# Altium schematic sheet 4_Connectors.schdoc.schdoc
size 309 x 223 mm; Symbol: Artery_A4; Device: Artery_A4; @Page Count: 4; @Create Date: 2024-01-02; @Page Name: Connectors; @Project Name: AT-START-L021; @Update Date: 2024-02-21; @Schematic Name: AT-START-L021_V1.0; @Page No: 4; Company: Artery Technology; Drawed: SD; Version: 1.0; Page Size: A4
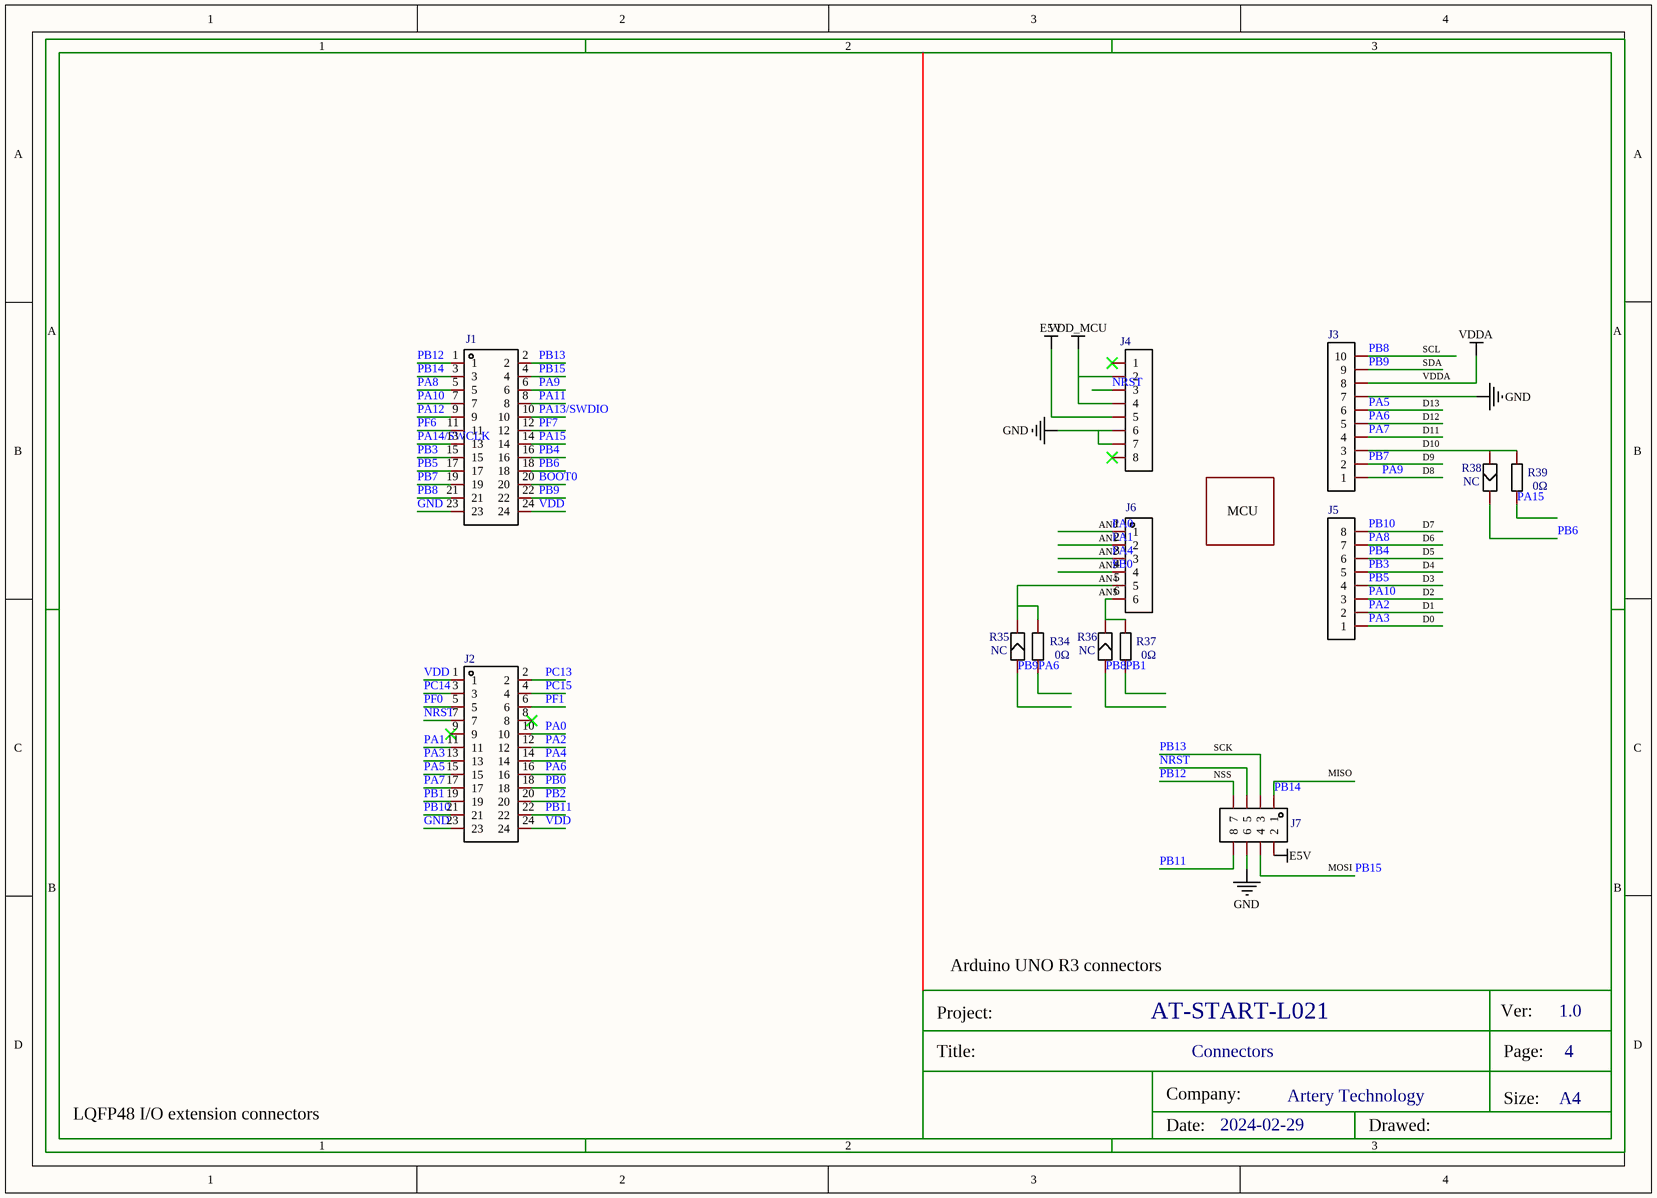
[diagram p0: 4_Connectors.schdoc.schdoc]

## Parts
J1  PZ254V-12-24P  [HDR-TH_24P-P2.54-V-M-R2-C12-S2.54]  (value not drawn)
J2  PZ254V-12-24P  [HDR-TH_24P-P2.54-V-M-R2-C12-S2.54]  (value not drawn)
J3  2.54-1*10P母  [AT-START-Connector 1x10]  (value not drawn)
J4  2.54-1*8P母环保  [AT-START-Connector 1x8]  (value not drawn)
J5  2.54-1*8P母环保  [AT-START-Connector 1x8]  (value not drawn)
J6  2.54-1*6P母  [AT-START-Connector 1x6]  (value not drawn)
J7  Header 4X2  [HDR2X4]  (value not drawn)
R34  value 0Ω  [R0603]  (hidden comment: 0603WAF0000T5E)
R35  NC  [SB-PAD]
R36  NC  [SB-PAD]
R37  value 0Ω  [R0603]  (hidden comment: 0603WAF0000T5E)
R38  NC  [SB-PAD]
R39  value 0Ω  [R0603]  (hidden comment: 0603WAF0000T5E)

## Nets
E5V: J4.5 J7.2
GND: J1.23 J2.23 J3.7 J4.6 J4.7 J7.6
VDD_MCU: J4.2 J4.4
VDDA: J3.8
BOOT0: J1.20
NRST: J2.7 J4.3 J7.5
PA0: J2.10 J6.1
PA1: J2.11 J6.2
PA2: J2.12 J5.2
PA3: J2.13 J5.1
PA4: J2.14 J6.3
PA5: J2.15 J3.6
PA6: J2.16 J3.5 R34.1
PA7: J2.17 J3.4
PA8: J1.5 J5.7
PA9: J1.6 J3.1
PA10: J1.7 J5.3
PA11: J1.8
PA12: J1.9
PA13/SWDIO: J1.10
PA14/SWCLK: J1.13
PA15: J1.14 R39.1
PB0: J2.18 J6.4
PB1: J2.19 R37.1
PB2: J2.20
PB3: J1.15 J5.5
PB4: J1.16 J5.6
PB5: J1.17 J5.4
PB6: J1.18 R38.2
PB7: J1.19 J3.2
PB8: J1.21 J3.10 R36.1
PB9: J1.22 J3.9 R35.1
PB10: J2.21 J5.8
PB11: J2.22 J7.8
PB12: J1.1 J7.7
PB13: J1.2 J7.3
PB14: J1.3 J7.1
PB15: J1.4 J7.4
PC13: J2.2
PC14: J2.3
PC15: J2.4
PF0: J2.5
PF1: J2.6
PF6: J1.11
PF7: J1.12
VDD: J1.24 J2.1 J2.24
NetJ3_3: J3.3 R38.1 R39.2
NetJ6_5: J6.5 R34.2 R35.2
NetJ6_6: J6.6 R36.2 R37.2

Not connected (* = marked no-connect by the designer): J2 8* 9*; J4 1* 8*

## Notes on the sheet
- SCL
- SDA
- VDDA
- D13
- D8
- D9
- D10
- D11
- D12
- (near J6) AN0
- (near J6) AN1
- MCU
- D6
- D7
- (near J6) AN2
- (near J6) AN3
- (near J6) AN4
- (near J6) AN5
- D1
- D2
- D3
- D4
- D5
- D0
- SCK
- (near J7) NSS
- MISO
- MOSI
- Arduino UNO R3 connectors
- LQFP48 I/O extension connectors
- 2024-02-29

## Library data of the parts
J1 J2 = PZ254V-12-24P: 间距:2.54mm;总PIN位数:24;排数:2;插针结构:2x12P;行距:2.54mm;安装类型:直插;圆针/方针:方针;额定电流:-;额定电压:-;配合针长度:6mm;塑高:2.5mm;端接针长度:3mm;触头材质:黄铜;触头镀层:-;工作温度范围:-40~+105;颜色:黑色;; Manufacturer: XFCN(台湾兴飞); Add into BOM: yes; Pitch: 2.54mm; Pin Structure: 2x12P; Circluar Pins/Square Pins: 方针
J3 = 2.54-1*10P母: Manufacturer: BOOMELE(博穆精密); Symbol: Header-Female-2.54_1x10; Add into BOM: yes; Pitch: 2.54mm; Number of Holes: 10; Holes Structure: 1x10P; Description: 间距:2.54mm;总孔位数:10;排数:1;插孔结构:1x10P;行距:-;安装类型:直插;塑高:-;触头材质:-;触头镀层:-;
J4 J5 = 2.54-1*8P母环保: Manufacturer: BOOMELE(博穆精密); Symbol: Header-Female-2.54_1x8; Add into BOM: yes; Pitch: 2.54mm; Number of Holes: 8; Holes Structure: 1x8P; Description: 间距:2.54mm;总孔位数:8;排数:1;插孔结构:1x8P;行距:-;安装类型:直插;塑高:-;触头材质:-;触头镀层:-;
J6 = 2.54-1*6P母: Manufacturer: BOOMELE(博穆精密); Symbol: Header-Female-2.54_1x6; Add into BOM: yes; Pitch: 2.54mm; Number of Holes: 6; Holes Structure: 1x6P; Description: 间距:2.54mm;总孔位数:6;排数:1;插孔结构:1x6P;行距:-;安装类型:直插;塑高:-;触头材质:-;触头镀层:-;
J7 = Header 4X2: Convert to PCB: yes
R34 R37 R39 = 0603WAF0000T5E: 电阻类型:厚膜电阻;阻值:0Ω;精度:±1%;功率:1/10W;温度系数:-;最大工作电压:75V;工作温度范围:-55~+155;; Manufacturer: UNI-ROYAL(厚声); Add into BOM: yes; Tolerance: ±1%; Power(Watts): 1/10W; Overload Voltage (Max): 75V
R35 R36 R38 = NC_SB-PAD: Convert to PCB: yes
